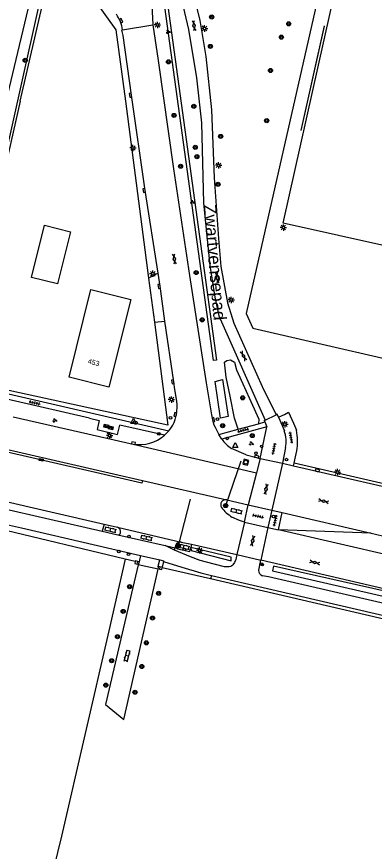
# Model space of a CAD drawing. Extents: x 128999 to 131010, y 395498 to 399007.
# Drawn here: x 129760.3 to 129830.6, y 396852.7 to 397016.6 of the extents above; entities that cross this region are included whole.
import ezdxf

# ---------------------------------------------------------------- set-up
doc = ezdxf.new("R2010")
doc.units = 0
for name, color, linetype in [('gg-afsc-hekwerk', 7, 'Continuous'), ('gg-afsc-muur', 7, 'Continuous'), ('gg-anno-huisnummerreeks BGT', 7, 'Continuous'), ('gg-anno-openbare ruimte label', 7, 'Continuous'), ('gg-bbg-bijgebouw', 7, 'Continuous'), ('gg-bbg-hoofdgebouw', 7, 'Continuous'), ('gg-knt-bronhoudergrens', 7, 'Continuous'), ('gg-knt-verharding', 7, 'Continuous'), ('gg-knt-verharding nz', 7, 'Continuous'), ('gg-kntw-bovenkant insteek waterloop', 7, 'Continuous'), ('gt-grn-groengrens', 7, 'Continuous'), ('gt-grn-vlakafsluiter', 7, 'Continuous'), ('gt-grn-weggrens', 7, 'Continuous'), ('gt-knt-lijn portaal', 7, 'Continuous'), ('gt-symb-boom', 7, 'Continuous'), ('gt-symb-brandkraan', 7, 'Continuous'), ('gt-symb-drukknoppaal', 7, 'Continuous'), ('gt-symb-gesloten verharding', 7, 'Continuous'), ('gt-symb-groenvak', 7, 'Continuous'), ('gt-symb-klinker verharding', 7, 'Continuous'), ('gt-symb-kolk', 7, 'Continuous'), ('gt-symb-kolk center center', 7, 'Continuous'), ('gt-symb-lichtmast', 7, 'Continuous'), ('gt-symb-portaalmast', 7, 'Continuous'), ('gt-symb-rioolschacht', 7, 'Continuous'), ('gt-symb-tegel verharding', 7, 'Continuous'), ('gt-symb-verkeersregelinstallatiekast', 7, 'Continuous'), ('gt-symb-verkeersregelinstallatiepaal', 7, 'Continuous'), ('gt-symb-waterafsluiter', 7, 'Continuous')]:
    doc.layers.add(name, color=color, linetype=linetype)

# ---------------------------------------------------------------- blocks, each defined once
blk = doc.blocks.new('gt0-BOOM')
at = {"layer": 'gt-symb-boom'}
for radius in [0.4, 0.2]:
    blk.add_circle((0, 0), radius, dxfattribs=at)
blk = doc.blocks.new('gt0-GESVH1')
at = {"layer": 'gt-symb-gesloten verharding'}
for p, q in [((-0.99, -0.26), (0.01, 0.24)), ((0.01, -0.26), (-0.99, 0.24)), ((0.01, 0.24), (1.01, -0.26)), ((1.01, 0.24), (0.01, -0.26))]:
    blk.add_line(p, q, dxfattribs=at)
blk = doc.blocks.new('gt0-LMAST')
at = {"layer": 'gt-symb-lichtmast'}
for p, q in [((-0.18, 0.17), (-0.45, 0.44)), ((-0.01, 0.25), (-0.01, 0.62)), ((0.17, 0.17), (0.44, 0.44)), ((-0.26, 0), (-0.63, 0)), ((-0.18, -0.18), (-0.45, -0.45)), ((-0.01, -0.25), (-0.01, -0.63)), ((0.44, -0.45), (0.17, -0.18)), ((0.24, 0), (0.62, 0))]:
    blk.add_line(p, q, dxfattribs=at)
blk.add_circle((-0.01, 0), 0.25, dxfattribs=at)
blk = doc.blocks.new('gt0-TEG1')
at = {"layer": 'gt-symb-tegel verharding'}
for p, q in [((-1.12, 0), (1.12, 0)), ((-0.9, -0.25), (-0.9, 0.25)), ((-0.45, -0.25), (-0.45, 0.25)), ((0, -0.25), (0, 0.25)), ((0.45, -0.25), (0.45, 0.25)), ((0.9, -0.25), (0.9, 0.25))]:
    blk.add_line(p, q, dxfattribs=at)
blk = doc.blocks.new('gt0-KOLK')
at = {"layer": 'gt-symb-kolk'}
blk.add_lwpolyline([(0, 0), (0.38, 0), (0.38, 0.4), (-0.38, 0.4), (-0.38, 0), (0, 0)], dxfattribs=at)
blk = doc.blocks.new('gt0-VIPAAL')
at = {"layer": 'gt-symb-verkeersregelinstallatiepaal'}
blk.add_circle((0, 0), 0.25, dxfattribs=at)
blk = doc.blocks.new('gt0-KL1')
at = {"layer": 'gt-symb-klinker verharding'}
for p, q in [((-1.15, 0.3), (1.15, 0.3)), ((-1, -0.3), (-1, 0.3)), ((-0.5, 0.3), (-0.5, 0.45)), ((0, -0.3), (0, 0.3)), ((0.5, 0.3), (0.5, 0.45)), ((1, -0.3), (1, 0.3)), ((-1.15, -0.3), (1.15, -0.3)), ((-0.5, -0.45), (-0.5, -0.3)), ((0.5, -0.45), (0.5, -0.3))]:
    blk.add_line(p, q, dxfattribs=at)
blk = doc.blocks.new('gt0-GRVAK')
at = {"layer": 'gt-symb-groenvak'}
for p, q in [((-0.11, 0.19), (-0.23, 0.24)), ((-0.18, 0.15), (0.09, 0.15)), ((-0.09, 0.21), (-0.16, 0.32)), ((-0.05, 0.21), (-0.05, 0.39)), ((0, 0.21), (0.06, 0.32)), ((0.01, 0.19), (0.13, 0.24)), ((0.26, -0.05), (0.2, 0.06)), ((0.31, -0.05), (0.31, 0.13)), ((0.35, -0.05), (0.41, 0.06)), ((-0.24, -0.23), (-0.36, -0.18)), ((-0.32, -0.26), (-0.05, -0.26)), ((-0.23, -0.21), (-0.29, -0.1)), ((-0.18, -0.2), (-0.18, -0.02)), ((-0.14, -0.21), (-0.07, -0.1)), ((-0.12, -0.23), (0, -0.18)), ((0.24, -0.07), (0.12, -0.02)), ((0.17, -0.11), (0.44, -0.11)), ((0.37, -0.07), (0.49, -0.02))]:
    blk.add_line(p, q, dxfattribs=at)
blk = doc.blocks.new('gt0-KOLKCC')
at = {"layer": 'gt-symb-kolk center center'}
blk.add_lwpolyline([(-0.38, 0.2), (0.37, 0.2), (0.37, -0.2), (-0.38, -0.2)], close=True, dxfattribs=at)
blk = doc.blocks.new('gt0-VRIKST')
at = {"layer": 'gt-symb-verkeersregelinstallatiekast'}
for p, q in [((-0.5, -0.25), (0.5, 0.25)), ((-0.5, 0.25), (0.5, -0.25))]:
    blk.add_line(p, q, dxfattribs=at)
blk.add_lwpolyline([(0.5, 0.25), (-0.5, 0.25), (-0.5, -0.25), (0.5, -0.25)], close=True, dxfattribs=at)
blk = doc.blocks.new('gt0-WAFSL')
at = {"layer": 'gt-symb-waterafsluiter'}
for p, q in [((-0.5, -0.33), (0, 0.67)), ((0, 0.67), (0.5, -0.33)), ((0.5, -0.33), (-0.5, -0.33))]:
    blk.add_line(p, q, dxfattribs=at)
blk = doc.blocks.new('gt0-BR')
at = {"layer": 'gt-symb-brandkraan'}
for centre, radius, start, end in [((-0.24, 0), 0.206, 107.5669, 252.4331), ((0.6, -2.66), 3, 106.892, 107.5669), ((0, -0.69), 0.938, 73.108, 106.892), ((-0.6, -2.66), 3, 72.4331, 73.108), ((0.24, 0), 0.206, 287.567, 72.4331), ((0.6, 2.66), 3, 252.4331, 253.108), ((0, 0.69), 0.938, 253.108, 286.8921), ((-0.6, 2.66), 3, 286.8921, 287.567)]:
    blk.add_arc(centre, radius, start, end, dxfattribs=at)
blk = doc.blocks.new('gt0-RS')
at = {"layer": 'gt-symb-rioolschacht'}
blk.add_lwpolyline([(-0.5, -0.5), (0.5, -0.5), (0.5, 0.5), (-0.5, 0.5)], close=True, dxfattribs=at)
blk.add_circle((0, 0), 0.375, dxfattribs=at)
blk = doc.blocks.new('gt0-DPAAL')
at = {"layer": 'gt-symb-drukknoppaal'}
blk.add_circle((0, 0), 0.25, dxfattribs=at)
blk = doc.blocks.new('gt0-PORTM')
at = {"layer": 'gt-symb-portaalmast'}
for radius in [0.4, 0.33, 0.27, 0.21, 0.15]:
    blk.add_circle((0, 0), radius, dxfattribs=at)

msp = doc.modelspace()

# ---------------------------------------------------------------- linework, layer by layer
at = {"layer": 'gg-afsc-hekwerk'}
for p, q in [((129761.06, 397000), (129766.12, 397022.1)), ((129779.85, 397014.04), (129781.69, 397000)), ((129820.72, 397014.78), (129816.13, 396994.27)), ((129820.73, 397014.76), (129816.14, 396994.25)), ((129761.06, 397000), (129748.55, 396945.4)), ((129781.69, 397000), (129786.2, 396965.74)), ((129786.2, 396965.74), (129786.26, 396965.22)), ((129786.26, 396965.22), (129787.4, 396956.6)), ((129781.67, 396910.05), (129751.85, 396917.18)), ((129781.67, 396910.05), (129751.85, 396917.18)), ((129782.48, 396909.86), (129781.67, 396910.05)), ((129782.48, 396909.86), (129781.67, 396910.05)), ((129783.65, 396909.58), (129782.48, 396909.86)), ((129783.65, 396909.58), (129782.48, 396909.86)), ((129798.43, 396906.18), (129788.93, 396908.38)), ((129798.43, 396906.18), (129788.93, 396908.38)), ((129852.09, 396893.73), (129798.43, 396906.18)), ((129852.09, 396893.73), (129798.43, 396906.18))]:
    msp.add_line(p, q, dxfattribs=at)
for points in [[(129766.12, 397022.1), (129775.83, 397019.59), (129779.85, 397014.04)], [(129787.4, 396956.6), (129790.05, 396936.4), (129748.55, 396945.4)]]:
    msp.add_lwpolyline(points, dxfattribs=at)
at = {"layer": 'gg-afsc-muur'}
msp.add_line((129788.92, 396908.48), (129788.48, 396908.57), dxfattribs=at)
for points in [[(129783.65, 396909.58), (129783.56, 396909.23), (129784.04, 396909.1), (129784.17, 396909.59)], [(129784.17, 396909.59), (129783.69, 396909.72), (129783.65, 396909.58)], [(129788.48, 396908.57), (129788.38, 396908.12), (129788.85, 396908.02), (129788.93, 396908.38)], [(129788.92, 396908.48), (129788.95, 396908.47), (129788.93, 396908.38)]]:
    msp.add_lwpolyline(points, dxfattribs=at)
at = {"layer": 'gg-bbg-bijgebouw'}
msp.add_lwpolyline([(129765.84, 396975.64), (129770.94, 396974.37), (129768.38, 396964.13), (129763.29, 396965.4), (129765.84, 396975.64)], dxfattribs=at)
at = {"layer": 'gg-bbg-hoofdgebouw'}
msp.add_lwpolyline([(129778.45, 396943.83), (129770.63, 396945.78), (129774.9, 396963.02), (129782.76, 396961.06), (129778.45, 396943.83)], dxfattribs=at)
at = {"layer": 'gg-knt-bronhoudergrens'}
msp.add_lwpolyline([(129781.67, 396910.05), (129778.44, 396895.99), (129769.18, 396855.65), (129737.18, 396725.5), (129717.68, 396643.44), (129691.8, 396649.59), (129693.26, 396655.75), (129690.58, 396656.38)], dxfattribs=at)
at = {"layer": 'gg-knt-verharding'}
for p, q in [((129781.16, 397014.01), (129787.08, 397015.01)), ((129788.16, 396966.2), (129786.26, 396965.22)), ((129787.4, 396956.6), (129789.44, 396956.8)), ((129625.69, 396951.83), (129777.5, 396916.93)), ((129625.38, 396950.49), (129777.13, 396915.52)), ((129676.72, 396950.45), (129785.06, 396925.49)), ((129791.81, 396941.01), (129791.36, 396943.81)), ((129809.15, 396937.38), (129811.33, 396938.42)), ((129759.64, 396938.01), (129783.24, 396932.65)), ((129803.84, 396935.56), (129807.85, 396936.66)), ((129807.85, 396936.66), (129809.1, 396937)), ((129809.1, 396937), (129809.51, 396936.04)), ((129811.77, 396937.93), (129812.92, 396935.25)), ((129789.38, 396934.39), (129780.58, 396936.39)), ((129789.38, 396934.39), (129790.22, 396935.26)), ((129800.03, 396934.53), (129803.84, 396935.56)), ((129809.51, 396936.04), (129800.64, 396933.62)), ((129808.16, 396929.85), (129809.51, 396936.04)), ((129800.64, 396933.62), (129800.03, 396934.53)), ((129805.39, 396930.57), (129802.54, 396931.79)), ((129813.17, 396931.97), (129812.55, 396928.88)), ((129808.16, 396929.85), (129812.55, 396928.88)), ((129812.55, 396928.88), (129814.71, 396928.38)), ((129814.71, 396928.38), (129814.84, 396928.92)), ((129814.71, 396928.38), (129853.34, 396919.49)), ((129741.94, 396920.63), (129761.31, 396916.18)), ((129801.61, 396921.68), (129805.82, 396920.7)), ((129805.08, 396917.35), (129805.82, 396920.7)), ((129805.82, 396920.7), (129810.45, 396919.66)), ((129810.45, 396919.66), (129809.67, 396916.3)), ((129810.45, 396919.66), (129812.5, 396919.19)), ((129811.75, 396915.82), (129812.5, 396919.19)), ((129812.5, 396919.19), (129829.95, 396915.16)), ((129777.5, 396916.93), (129777.13, 396915.52)), ((129777.5, 396916.93), (129780.14, 396916.31)), ((129805.08, 396917.35), (129809.67, 396916.3)), ((129761.31, 396916.18), (129784.68, 396910.78)), ((129777.13, 396915.52), (129780.22, 396914.81)), ((129780.14, 396916.31), (129792.68, 396913.42)), ((129809.67, 396916.3), (129811.75, 396915.82)), ((129921.93, 396890.37), (129811.75, 396915.82)), ((129780.22, 396914.81), (129789.53, 396912.71)), ((129829.95, 396915.16), (129922.61, 396893.79)), ((129789.53, 396912.71), (129791.46, 396912.27)), ((129791.35, 396911.83), (129789.53, 396912.71)), ((129791.35, 396911.83), (129791.46, 396912.27)), ((129791.46, 396912.27), (129791.53, 396912.54)), ((129791.53, 396912.75), (129791.53, 396912.54)), ((129792.68, 396913.42), (129794.67, 396912.98)), ((129794.53, 396912.37), (129794.52, 396912.33)), ((129794.67, 396912.98), (129794.53, 396912.37)), ((129794.67, 396912.98), (129803.61, 396910.95)), ((129784.68, 396910.78), (129784.38, 396909.54)), ((129784.68, 396910.78), (129788.44, 396909.91)), ((129803.61, 396910.95), (129808.32, 396909.88)), ((129784.38, 396909.54), (129784.24, 396908.96)), ((129788.14, 396908.65), (129788.44, 396909.91)), ((129788.48, 396908.57), (129788.14, 396908.65)), ((129788.44, 396909.91), (129789.2, 396909.73)), ((129789.17, 396909.62), (129788.92, 396908.48)), ((129789.2, 396909.73), (129789.17, 396909.62)), ((129807.88, 396907.89), (129808.32, 396909.88)), ((129835.03, 396903.64), (129808.32, 396909.88)), ((129781.36, 396878.54), (129788.15, 396908.06)), ((129798.58, 396906.82), (129798.43, 396906.18)), ((129798.58, 396906.82), (129848.6, 396895.2))]:
    msp.add_line(p, q, dxfattribs=at)
for points in [[(129825.29, 397032.6), (129921.34, 397011.27), (129908.72, 396954.66), (129812.68, 396976.03), (129825.29, 397032.6)], [(129792.19, 397022.21), (129794.07, 397014.1), (129795.64, 397004.59), (129796.62, 396995.78), (129797.04, 396980), (129798.28, 396967.75), (129799.29, 396961.49), (129800.04, 396957.88), (129809.15, 396937.38)], [(129787.08, 397015.01), (129787.18, 397015.04), (129786.95, 397018.83)], [(129795.33, 397019.93), (129796.3, 397015.84), (129797.52, 397008.81), (129798.62, 396998.31), (129799.14, 396984.93), (129799.99, 396973.04), (129800.47, 396967.52), (129801.78, 396960.38), (129803, 396956.43), (129808.54, 396943.97), (129811.33, 396938.42)], [(129788.16, 396966.2), (129785.6, 396982.49), (129782.88, 397001.2), (129781.23, 397012.9), (129780.99, 397013.99), (129781.16, 397014.01)], [(129787.08, 397015.01), (129788.12, 397007.97), (129791.15, 396986.71), (129794.29, 396965.74), (129797.59, 396944.72)], [(129789.44, 396956.8), (129788.52, 396963.65), (129788.16, 396966.2)], [(129791.36, 396943.81), (129791.19, 396944.9), (129789.44, 396956.8)], [(129722.31, 396950.63), (129722.37, 396950.88), (129790.22, 396935.26)], [(129785.06, 396925.49), (129784.96, 396925.01), (129698.73, 396944.85), (129695.66, 396945.3), (129693.67, 396945.52), (129677.69, 396946.8), (129675.91, 396947.01)], [(129774.65, 396937.76), (129743.84, 396944.84), (129743.69, 396944.28)], [(129797.59, 396944.72), (129798.59, 396938.4), (129798.81, 396937.4), (129799.09, 396936.41)], [(129811.77, 396937.93), (129811.52, 396938.52), (129811.33, 396938.42)], [(129811.77, 396937.93), (129812.51, 396938.26), (129812.95, 396938.47), (129813.76, 396938.92), (129814.74, 396936.79), (129815.32, 396935.37)], [(129774.65, 396937.76), (129776.55, 396937.31), (129776.14, 396935.51), (129780.15, 396934.52), (129780.58, 396936.39)], [(129809.1, 396937), (129809.05, 396937.34), (129809.15, 396937.38)], [(129790.22, 396935.26), (129790.64, 396935.8), (129791.02, 396936.36)], [(129799.09, 396936.41), (129799.31, 396935.95), (129800.03, 396934.53)], [(129805.39, 396930.57), (129807.45, 396930), (129808.16, 396929.85)], [(129814.84, 396928.92), (129815, 396929.54), (129815.36, 396931.32)], [(129805.08, 396917.35), (129804.1, 396917.64), (129802.63, 396918.33)], [(129791.95, 396912.09), (129794.35, 396911.53), (129794.52, 396912.33)], [(129803.61, 396910.95), (129803.42, 396910), (129803.16, 396909.42), (129802.83, 396908.92), (129802.62, 396908.75), (129802.39, 396908.64), (129802.07, 396908.55), (129801.71, 396908.52), (129801.15, 396908.56), (129797.6, 396909.48), (129796.38, 396909.82), (129794.48, 396910.5), (129791.35, 396911.83)], [(129784.24, 396908.96), (129783.16, 396904.48), (129777.81, 396881.51)], [(129788.15, 396908.06), (129788.23, 396908.4), (129788.11, 396908.52), (129788.14, 396908.65)], [(129854.94, 396896.15), (129809.83, 396906.58), (129808.62, 396906.81)]]:
    msp.add_lwpolyline(points, dxfattribs=at)
for centre, radius, start, end in [((129772.54, 397012.41), 8.77, 10.5082, 32.2919), ((129783.37, 396940.04), 8.5, 334.2906, 6.5333), ((129807.16, 396933.16), 6.12, 348.7489, 19.9577), ((129803.94, 396933.23), 11.57, 350.4757, 10.6546), ((129784.48, 396939.96), 7.42, 260.3496, 311.3515), ((129807.57, 396938.91), 8.72, 217.3707, 234.7784), ((129801.4, 396920.72), 0.985, 77.8179, 210.8781), ((129807.39, 396925.65), 8.74, 218.5044, 236.9839), ((129779.83, 396915.43), 0.933, 346.5559, 70.3198), ((129780.24, 396915.32), 0.509, 268.011, 348.9563), ((129792.52, 396912.38), 1.06, 81.4472, 159.654), ((129792.08, 396912.64), 0.566, 190.1331, 255.908), ((129808.91, 396907.8), 1.04, 175.0977, 253.4234)]:
    msp.add_arc(centre, radius, start, end, dxfattribs=at)
at = {"layer": 'gg-knt-verharding nz'}
for p, q in [((129808.16, 396929.85), (129807.43, 396926.98)), ((129812.55, 396928.88), (129810.45, 396919.66)), ((129807.43, 396926.98), (129805.82, 396920.7)), ((129805.08, 396917.35), (129803.61, 396910.95)), ((129809.67, 396916.3), (129808.32, 396909.88))]:
    msp.add_line(p, q, dxfattribs=at)
msp.add_lwpolyline([(129789.17, 396909.62), (129792.81, 396908.47), (129796.53, 396907.38), (129798.58, 396906.82)], dxfattribs=at)
at = {"layer": 'gg-kntw-bovenkant insteek waterloop'}
msp.add_lwpolyline([(129745.86, 396948.32), (129748.7, 396947.67), (129756.78, 396983.29), (129765.08, 397020.46), (129763.16, 397020.93), (129745.86, 396948.32)], dxfattribs=at)
at = {"layer": 'gt-grn-groengrens'}
for p, q in [((129855.03, 396919.61), (129814.84, 396928.92)), ((129829.95, 396915.16), (129811.75, 396915.82))]:
    msp.add_line(p, q, dxfattribs=at)
for points in [[(129820.63, 397025.22), (129805.42, 396958.29), (129806.73, 396955.42), (129846.47, 396946.23)], [(129789.46, 397018.57), (129790.05, 397018.66), (129799.57, 396949.14), (129798.98, 396949.07), (129789.46, 397018.57)], [(129803.84, 396935.56), (129803.13, 396937.75), (129802.29, 396942.09), (129801.52, 396945.79), (129801.17, 396948.73), (129801.59, 396949.08), (129802.36, 396949.22), (129803.13, 396948.73), (129803.55, 396947.26), (129807.89, 396937.54), (129807.85, 396936.66)], [(129799.34, 396944.95), (129800.79, 396945.37), (129801.86, 396938.05), (129800.39, 396937.73), (129799.34, 396944.95)], [(129794.52, 396912.33), (129794.63, 396911.73), (129802.5, 396909.74), (129802.49, 396910.47), (129794.53, 396912.37)], [(129810.77, 396908.66), (129810.58, 396907.78), (129835.44, 396902.06), (129835.56, 396903.08), (129810.77, 396908.66)]]:
    msp.add_lwpolyline(points, dxfattribs=at)
at = {"layer": 'gt-grn-vlakafsluiter'}
for p, q in [((129784.38, 396909.54), (129784.17, 396909.59)), ((129777.81, 396881.51), (129781.36, 396878.54))]:
    msp.add_line(p, q, dxfattribs=at)
at = {"layer": 'gt-grn-weggrens'}
for p, q in [((129783.24, 396932.65), (129807.43, 396926.98)), ((129785.06, 396925.49), (129801.61, 396921.68)), ((129788.15, 396908.06), (129784.24, 396908.96))]:
    msp.add_line(p, q, dxfattribs=at)
at = {"layer": 'gt-knt-lijn portaal'}
for p, q in [((129801.4, 396920.58), (129804.46, 396929.35)), ((129792.12, 396912.64), (129794.51, 396921.85))]:
    msp.add_line(p, q, dxfattribs=at)

# ---------------------------------------------------------------- block references
at = {"layer": 'gt-symb-boom'}
for p in [(129798.65, 397016.54), (129798.39, 397010.77), (129762.02, 397008.03), (129795.14, 396999), (129791.26, 396997.22), (129800.41, 396993.09), (129795.42, 396990.94), (129795.75, 396989.11), (129792.54, 396987.22), (129799.89, 396983.69), (129795.6, 396966.35), (129796.77, 396957.06), (129804.75, 396941.74), (129800.8, 396936.26), (129806.61, 396934.32), (129782.52, 396904.65), (129788.22, 396903.36), (129781.26, 396899.79), (129780.15, 396894.83), (129785.82, 396893.62), (129779, 396890.1), (129784.92, 396888.97), (129777.85, 396885.3), (129783.59, 396883.92)]:
    msp.add_blockref('gt0-BOOM', p, dxfattribs=at)
for p, rotation in [((129813.78, 397015.2), -101.36613785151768), ((129812.34, 397012.58), -101.36613785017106), ((129790.17, 397007.73), 6.66296362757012), ((129810.2, 397006.03), -101.36613785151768), ((129809.45, 396996.18), -101.36613785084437), ((129787.02, 396898.48), 90)]:
    msp.add_blockref('gt0-BOOM', p, dxfattribs=dict(at, rotation=rotation))
at = {"layer": 'gt-symb-brandkraan', "rotation": -12.715336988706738}
msp.add_blockref('gt0-BR', (129783.63, 396936.88), dxfattribs=at)
at = {"layer": 'gt-symb-drukknoppaal'}
for p, rotation in [((129808.47, 396932.2), -12.957719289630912), ((129793.29, 396911.99), -12.957719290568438), ((129780.41, 396911.55), -12.957719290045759), ((129808.36, 396909.1), -12.957719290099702)]:
    msp.add_blockref('gt0-DPAAL', p, dxfattribs=dict(at, rotation=rotation))
at = {"layer": 'gt-symb-gesloten verharding'}
for p, rotation in [((129795.19, 397014.85), -81.65913313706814), ((129791.31, 396968.98), 98.91603673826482), ((129799.75, 396965.32), -80.84860398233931), ((129804.9, 396949.99), -63.25557979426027), ((129809.31, 396923.8), 77.22875743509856), ((129820.63, 396921.46), -12.938810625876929), ((129806.7, 396913.67), -102.93881062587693), ((129818.87, 396909.42), -12.938810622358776)]:
    msp.add_blockref('gt0-GESVH1', p, dxfattribs=dict(at, rotation=rotation))
at = {"layer": 'gt-symb-groenvak'}
for p in [(129790.1, 397013.65), (129767.83, 396937.32)]:
    msp.add_blockref('gt0-GRVAK', p, dxfattribs=at)
for p, rotation in [((129794.88, 396980.15), -7.068140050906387), ((129806.42, 396932.77), -7.068140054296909)]:
    msp.add_blockref('gt0-GRVAK', p, dxfattribs=dict(at, rotation=rotation))
at = {"layer": 'gt-symb-klinker verharding'}
for p, rotation in [((129803.5, 396919.53), -12.702731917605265), ((129778.77, 396915.86), -12.702731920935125), ((129785.86, 396914.25), -12.702731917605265), ((129793.16, 396912.52), -12.702731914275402), ((129782.04, 396891.07), 74.5188140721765)]:
    msp.add_blockref('gt0-KL1', p, dxfattribs=dict(at, rotation=rotation))
at = {"layer": 'gt-symb-kolk'}
for p, rotation in [((129780.66, 397015.72), -67.84741349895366), ((129782.88, 397001.2), 98.2758928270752), ((129785.6, 396982.49), 98.91603673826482), ((129788.52, 396963.65), 97.64386978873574), ((129791.19, 396944.9), 99.09480497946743), ((129791.71, 396938.42), 78.9933358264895), ((129798.81, 396937.39), -75.46349079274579), ((129783.24, 396932.65), -12.535023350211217), ((129807.45, 396930), -12.354826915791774), ((129819.37, 396927.3), -13.063337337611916)]:
    msp.add_blockref('gt0-KOLK', p, dxfattribs=dict(at, rotation=rotation))
at = {"layer": 'gt-symb-kolk center center', "rotation": 167.22875743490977}
msp.add_blockref('gt0-KOLKCC', (129765.16, 396929.56), dxfattribs=at)
at = {"layer": 'gt-symb-lichtmast'}
for p in [(129788, 397014.98), (129797.26, 397014.29), (129783.19, 396990.82), (129800, 396987.41), (129812.73, 396975.2), (129787.09, 396966.11), (129802.49, 396960.96), (129790.75, 396941.41), (129813.03, 396936.56), (129778.6, 396934.36), (129823.36, 396927.15), (129796.29, 396911.77)]:
    msp.add_blockref('gt0-LMAST', p, dxfattribs=at)
at = {"layer": 'gt-symb-portaalmast'}
for p in [(129801.4, 396920.58), (129792.12, 396912.64)]:
    msp.add_blockref('gt0-PORTM', p, dxfattribs=at)
at = {"layer": 'gt-symb-rioolschacht', "rotation": 75.17189147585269}
msp.add_blockref('gt0-RS', (129805.35, 396929.1), dxfattribs=at)
at = {"layer": 'gt-symb-tegel verharding'}
for p, rotation in [((129763.9, 396940.76), -13.007504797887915), ((129804.87, 396935.36), 15.24507033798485), ((129814.21, 396933.96), -80.20785375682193), ((129810.87, 396931.73), 78.57767893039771), ((129807.76, 396918.5), -12.702731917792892), ((129811.15, 396917.62), 77.58922528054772)]:
    msp.add_blockref('gt0-TEG1', p, dxfattribs=dict(at, rotation=rotation))
at = {"layer": 'gt-symb-verkeersregelinstallatiekast'}
for p, rotation in [((129777.97, 396936.18), -12.957719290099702), ((129778.83, 396935.85), 167.04228070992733)]:
    msp.add_blockref('gt0-VRIKST', p, dxfattribs=dict(at, rotation=rotation))
at = {"layer": 'gt-symb-verkeersregelinstallatiepaal'}
for p, rotation in [((129790.55, 396937.81), -12.957719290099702), ((129799.77, 396937.54), -12.957719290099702), ((129788.25, 396934.68), -12.95771929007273), ((129801.7, 396933.77), -12.957719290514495), ((129807.34, 396930.86), -12.957719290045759), ((129813.35, 396929.61), -12.957719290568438), ((129810.78, 396918.43), -12.957719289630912), ((129782.4, 396914.51), -12.957719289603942), ((129782.32, 396911.01), -12.95771929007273), ((129808.6, 396908.99), -12.957719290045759)]:
    msp.add_blockref('gt0-VIPAAL', p, dxfattribs=dict(at, rotation=rotation))
at = {"layer": 'gt-symb-waterafsluiter'}
for p in [(129783.26, 396937.05), (129803.27, 396932.33)]:
    msp.add_blockref('gt0-WAFSL', p, dxfattribs=at)

# ---------------------------------------------------------------- texts
at = {"layer": 'gg-anno-huisnummerreeks BGT'}
msp.add_text('453', height=1, rotation=346, dxfattribs=at).set_placement((129774.24, 396948.49))
at = {"layer": 'gg-anno-openbare ruimte label'}
msp.add_text('Zwartvensepad', height=2.5, rotation=275, dxfattribs=at).set_placement((129797.05, 396979.63))

doc.saveas('drawing.dxf')
